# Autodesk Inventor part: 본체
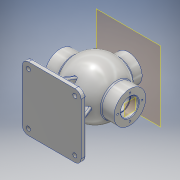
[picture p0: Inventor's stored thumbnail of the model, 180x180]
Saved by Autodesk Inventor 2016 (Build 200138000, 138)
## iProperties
Created: 2017-01
Part Number: 본체
Material: 알루미늄 6061
Document SubType Name: Modeling
Designer: Administrator
Density: 2.7 g/cm^3
Appearance: 알루미늄 - 평지
Mass: 1492.9 g
Surface Area: 1170.5 cm^2
Volume: 552.927 cm^3
Author: Administrator
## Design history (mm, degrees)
sketch "스케치1"
  geometry: L1 (57.5, 62.5)-(-57.5, 62.5); L2 (-57.5, 62.5)-(-57.5, -62.5); L3 (-57.5, -62.5)-(57.5, -62.5); L4 (57.5, -62.5)-(57.5, 62.5); 1 further point
  constraints: 8 end point, 2 parallel, 1 horizontal, 1 perpendicular
  dimensions: "d0" = 115 distance of L3.end L2.end; "d1" = 125 distance of L2.end L1.end; "d2" = 57.5 distance from line of point (0, 0) L4; "d3" = 62.5 distance from line of L1 point (0, 0)
extrude "돌출1" new body sketch "스케치1" stored distance "d4" = 10; taper "d5" = 0 deg
sketch "스케치2"
  geometry: 1 further point
sketch "스케치3"
  geometry: L1 (-5, -62.5)-(-5, 62.5) reference; L2 (-5, -62.5)-(5, -62.5) reference; L3 (49.016, -43)-(49.016, 43); L4 (80, 0)-(80, -53); L5 (80, 0)-(80, 53); A1 r 53 centre (80, 0) between (80, -53) and (80, 53); 1 further point
  constraints: 6 end point, 2 point on circle, 2 vertical, 1 centre point, 1 point on line
  dimensions: "d6" = 106 diameter of A1; "d7" = 85 distance from line of L4.start L1; "d8" = 62.5 distance from line of L4.start L2
revolve "회전1" sketch "스케치3" stored, may be unused: angle "d10" = 90 deg
sketch "스케치4"
  geometry: L1 (0, 80)-(-100.148, 80); L2 (-53, 80)-(-68, 80); L3 (-68, 80)-(-68, 111); L4 (-68, 111)-(-42.988, 111); A1 r 53 centre (0, 80) between (-53, 80) and (-42.988, 111) reference; 1 further point
  constraints: 8 end point, 2 perpendicular, 2 point on circle, 2 point on line, 1 horizontal
  dimensions: "d11" = 15 distance of L2.start L2.end; "d12" = 31 distance of L2.end L3.end
revolve "회전2" sketch "스케치4" stored, may be unused: angle "d13" = 90 deg
sketch "스케치5"
  geometry: L1 (-57.5, -5)-(57.5, -5) reference; L2 (57.5, -5)-(57.5, 5) reference; L3 (0, 80)-(-68, 80); L4 (-68, 49)-(-68, 111) reference; L5 (0, 80)-(68, 80); L6 (68, 49)-(68, 111) reference; L7 (-68, 80)-(-68, 97.5); L8 (-68, 97.5)-(-39.278, 97.5); L9 (68, 80)-(68, 97.5); L10 (68, 97.5)-(39.278, 97.5); A1 r 43 centre (0, 80) between (39.278, 97.5) and (-39.278, 97.5); 1 further point
  constraints: 12 end point, 2 midpoint, 2 point on circle, 2 point on line, 1 centre point, 1 horizontal, 1 perpendicular
  dimensions: "d14" = 86 diameter of A1; "d15" = 85 distance from line of L3.start L1; "d16" = 57.5 distance from line of L3.start L2; "d17" = 17.5 distance of L3.end L7.end
revolve "회전3" sketch "스케치5" stored, may be unused: angle "d18" = 90 deg
node "작업 평면1"
sketch "스케치6"
  geometry: C1 r 27 at (0, 0); 1 further point
  constraints: 1 centre point, 1 coincident
  dimensions: "d20" = 54 diameter of C1
extrude "돌출2" join sketch "스케치6" stored distance "d21" = 10; taper "d22" = 0 deg
sketch "스케치7"
  geometry: C1 r 13 at (0, 0); 1 further point
  constraints: 1 centre point, 1 coincident
  dimensions: "d23" = 26 diameter of C1
extrude "돌출3" cut sketch "스케치7" distance "d24" = 40; taper "d25" = 0 deg
fillet "모깎기1" dims "d26" = 12
fillet "모깎기2" dims "d27" = 12
sketch "스케치8"
  geometry: A1 r 12 centre (45.5, -50.5) between (45.5, -62.5) and (57.5, -50.5) reference; A2 r 12 centre (-45.5, -50.5) between (-57.5, -50.5) and (-45.5, -62.5) reference; A3 r 12 centre (45.5, 50.5) between (57.5, 50.5) and (45.5, 62.5) reference; A4 r 12 centre (-45.5, 50.5) between (-45.5, 62.5) and (-57.5, 50.5) reference; 5 further points
  constraints: 4 coincident
hole "구멍1" sketch "스케치8" at (45.5, -50.5), (-45.5, -50.5), (45.5, 50.5), (-45.5, 50.5) diameter "d28" = 8; stored, may be unused: countersink angle "d32" = 90 deg, drill point angle "d34" = 118 deg; dims "d29" = 6, "d30" = 12, "d31" = 3, "d33" = 8
fillet "모깎기3" dims "d35" = 3
sketch "스케치9"
  geometry: L1 (5, 50.5)-(5, -50.5) reference; L2 (5, 52.5)-(38.993, 38.766); L3 (5, 52.5)-(41.663, 52.5); L4 (5, -52.5)-(39.391, -38.605); L5 (5, -52.5)-(42.092, -52.5); L6 (5, 52.5)-(5, -52.5); L7 (2, -50.5)-(2, 50.5) reference; L8 (2, 62.5)-(-5, 62.5) reference; L9 (-5, -62.5)-(2, -62.5) reference; L10 (38.993, 38.766)-(42.426, 37.379); L11 (39.391, -38.605)-(42.426, -37.379); L12 (5, 52.5)-(5, -52.5); L13 (5, 56.5)-(5, 44.5) reference; A1 r 53 centre (80, 0) between (125.607, 27) and (125.607, -27) reference; 1 further point
  constraints: 16 end point, 3 point on line, 2 equal length, 2 horizontal, 2 point on circle, 1 collinear, 1 parallel
  dimensions: "d36" = 22 deg angle of L2 L3; "d37" = 22 deg angle of L5 L4; "d38" = 10 distance between parallel lines of L3 L8; "d39" = 10 distance from line of L9 L4.start
extrude "돌출4" join sketch "스케치9" stored distance "d40" = 8; taper "d41" = 0 deg
sketch "스케치10"
  geometry: 1 further point
sketch "스케치11"
  geometry: L1 (57.5, -5)-(57.5, 2) reference; L2 (57.5, 2)-(47.5, 2); L3 (45.5, 2)-(-45.5, 2) reference; L4 (47.5, 2)-(47.5, 5); L5 (47.5, 5)-(33.205, 40.382); L6 (47.5, 5)-(85.661, 5); 1 further point
  constraints: 9 end point, 1 collinear, 1 equal length, 1 horizontal, 1 perpendicular
  dimensions: "d42" = 10 distance of L1.end L2.end; "d43" = 112 deg angle of L6 L5
feature "리브1" sketch "스케치11" dims "d44" = 1, "d45" = 8, "d46" = 0, "d47" = 0, "d48" = 1, "d49" = 1
sketch "스케치12"
  geometry: A1 r 22.5 centre (0, 0) between (0, 22.5) and (-22.5, 0); 3 further points
  constraints: 4 point on circle, 1 centre point
  dimensions: "d50" = 45 diameter of A1
hole "구멍2" sketch "스케치12" at (0, 22.5), (-22.5, 0), (0, -22.5), (22.5, 0) diameter "d51" = 3.242; stored, may be unused: countersink angle "d55" = 90 deg, drill point angle "d57" = 118 deg; dims "d52" = 12, "d53" = 12, "d54" = 3, "d56" = 15
node "작업 평면2"
sketch "스케치14"
  geometry: L1 (0, -37.379)-(0, -4) reference; A1 r 20 centre (0, 0) between (-20, 0) and (0, -20); 3 further points
  constraints: 4 point on circle, 1 centre point, 1 coincident, 1 point on line
  dimensions: "d69" = 40 diameter of A1
hole "구멍4" sketch "스케치14" at (-20, 0), (0, 20), (20, 0), (0, -20) diameter "d70" = 3.242; stored, may be unused: countersink angle "d74" = 90 deg, drill point angle "d76" = 118 deg; dims "d71" = 9, "d72" = 12, "d73" = 3, "d75" = 11
sketch "스케치15"
  geometry: L1 (72.5, 150)-(18.5, 150) reference; L2 (18.5, 150)-(18.5, 130.607); L3 (18.5, 150)-(18.5, 130.607) reference; 2 further points
  constraints: 2 end point, 1 point on line, 1 other
  dimensions: "d77" = 10 distance from line of point (45.5, 140) L1; "d78" = 27 distance from line of point (45.5, 140) L2
sketch "스케치16"
  geometry: L1 (53, 80)-(68, 80); L2 (68, 80)-(68, 111); L3 (68, 111)-(42.988, 111); A1 r 53 centre (0, 80) between (33.719, 39.109) and (-33.719, 39.109) reference; 1 further point
  constraints: 6 end point, 2 point on circle, 1 horizontal, 1 perpendicular, 1 vertical
  dimensions: "d79" = 15 distance of L1.start L1.end; "d80" = 31 distance of L1.end L2.end
revolve "회전4" sketch "스케치16" stored, may be unused: angle "d81" = 90 deg
sketch "스케치17"
  geometry: L1 (68, 49)-(68, 111) reference; L2 (68, 97.5)-(52, 97.5); L3 (39.278, 97.5)-(50.027, 97.5) reference; L4 (68, 80)-(68, 97.5); L5 (68, 80)-(39.278, 80); L6 (39.278, 62.5)-(39.278, 97.5) reference; L7 (39.278, 80)-(39.278, 97.5); L8 (52, 97.5)-(52, 98.5); L9 (52, 98.5)-(50.25, 98.5); L10 (50.25, 98.5)-(50.25, 97.5); L11 (50.25, 97.5)-(39.278, 97.5); L12 (50.027, 97.5)-(50.027, 62.5) reference; 1 further point
  constraints: 16 end point, 4 perpendicular, 2 collinear, 2 midpoint, 1 horizontal, 1 point on line, 1 vertical
  dimensions: "d82" = 16 distance of L2.start L2.end; "d83" = 1 distance of L2.end L8.end; "d84" = 1.75 distance of L8.end L9.end; "d85" = 1 distance of L9.end L10.end; "d110" = 17.5 distance between parallel lines of L5 L2
revolve "회전5" sketch "스케치17" stored, may be unused: angle "d86" = 90 deg
feature "엠보싱1" dims "d87" = 0.5, "d88" = 0
sketch "스케치18" dims "d89" = 48
  geometry: 3 further points
  constraints: 1 vertical alignment, 2 other
hole "구멍5" sketch "스케치18" at (0, 24) diameter "d90" = 3.242; stored, may be unused: countersink angle "d94" = 90 deg, drill point angle "d96" = 118 deg; dims "d91" = 16, "d92" = 12, "d93" = 3, "d95" = 19
fillet "모깎기4" dims "d100" = 3
fillet "모깎기5" dims "d101" = 3
fillet "모깎기6" dims "d102" = 3
chamfer "모따기1" distance "d103" = 1; stored, may be unused: second distance "d104" = 2, angle "d105" = 45 deg
fillet "모깎기7" dims "d106" = 3
chamfer "모따기2" distance "d107" = 1; stored, may be unused: second distance "d108" = 2, angle "d109" = 45 deg
node "솔리드1"
mirror "대칭2"
pattern_circular "원형 패턴2" dims angle "d98" = 360 deg
